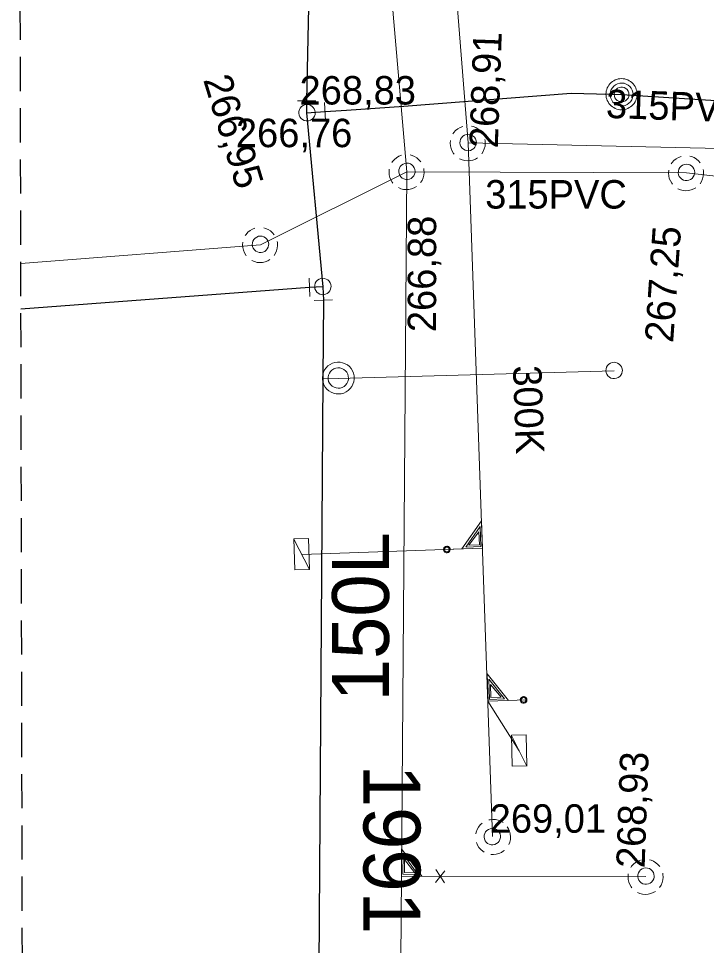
# Model space of a CAD drawing. Extents: x -732074 to -731966, y -1048695 to -1047982.
# Drawn here: x -731995.54 to -731976.2, y -1048660.19 to -1048634.13 of the extents above; entities that cross this region are included whole.
import ezdxf

# ---------------------------------------------------------------- set-up
doc = ezdxf.new("R2010")
doc.units = 0
doc.header["$LTSCALE"] = 0.32
doc.linetypes.add('MEDIUM_DASHED', pattern=[4.5, 3, -1.5])
doc.layers.add('1', color=7, linetype='Continuous')
for name, color, linetype, lineweight in [('18', 7, 'Continuous', 13), ('20', 7, 'Continuous', 13), ('49', 7, 'Continuous', 13), ('63', 7, 'MEDIUM_DASHED', 25), ('8', 7, 'Continuous', 13)]:
    doc.layers.add(name, color=color, linetype=linetype, lineweight=lineweight)

msp = doc.modelspace()

# ---------------------------------------------------------------- linework, layer by layer
at = {"layer": '18'}
for p, q in [((-731987.804, -1048648.765), (-731987.362, -1048649.624)), ((-731981.679, -1048654.282), (-731981.249, -1048655.147)), ((-731983.55, -1048658.088), (-731983.821, -1048658.421)), ((-731983.564, -1048658.426), (-731983.805, -1048658.053))]:
    msp.add_line(p, q, dxfattribs=at)
for points in [[(-731983.052, -1048637.166), (-731983.123, -1048637.194), (-731983.19, -1048637.233), (-731983.25, -1048637.281), (-731983.301, -1048637.338), (-731983.325, -1048637.372)], [(-731982.511, -1048637.349), (-731982.561, -1048637.291), (-731982.619, -1048637.241), (-731982.684, -1048637.2), (-731982.755, -1048637.171), (-731982.804, -1048637.157)], [(-731983.397, -1048637.558), (-731983.402, -1048637.635), (-731983.397, -1048637.712), (-731983.38, -1048637.787), (-731983.352, -1048637.858), (-731983.311, -1048637.924), (-731983.296, -1048637.946)], [(-731982.516, -1048637.935), (-731982.475, -1048637.87), (-731982.444, -1048637.8), (-731982.424, -1048637.725), (-731982.417, -1048637.649), (-731982.422, -1048637.572), (-731982.428, -1048637.537)], [(-731984.773, -1048637.977), (-731984.844, -1048638.005), (-731984.911, -1048638.044), (-731984.971, -1048638.092), (-731985.022, -1048638.149), (-731985.046, -1048638.183)], [(-731984.232, -1048638.16), (-731984.282, -1048638.102), (-731984.34, -1048638.052), (-731984.405, -1048638.011), (-731984.476, -1048637.982), (-731984.525, -1048637.968)], [(-731976.913, -1048638.007), (-731976.984, -1048638.035), (-731977.051, -1048638.074), (-731977.111, -1048638.122), (-731977.162, -1048638.179), (-731977.186, -1048638.213)], [(-731976.372, -1048638.19), (-731976.422, -1048638.132), (-731976.48, -1048638.082), (-731976.545, -1048638.041), (-731976.616, -1048638.012), (-731976.665, -1048637.998)], [(-731983.139, -1048638.075), (-731983.069, -1048638.106), (-731982.994, -1048638.125), (-731982.918, -1048638.132), (-731982.841, -1048638.127), (-731982.766, -1048638.11), (-731982.694, -1048638.082), (-731982.634, -1048638.047)], [(-731985.118, -1048638.369), (-731985.124, -1048638.446), (-731985.119, -1048638.523), (-731985.102, -1048638.598), (-731985.073, -1048638.669), (-731985.032, -1048638.735), (-731985.017, -1048638.757)], [(-731984.237, -1048638.746), (-731984.196, -1048638.681), (-731984.165, -1048638.611), (-731984.146, -1048638.536), (-731984.138, -1048638.46), (-731984.143, -1048638.383), (-731984.149, -1048638.348)], [(-731977.258, -1048638.399), (-731977.264, -1048638.476), (-731977.259, -1048638.553), (-731977.242, -1048638.628), (-731977.213, -1048638.699), (-731977.173, -1048638.765), (-731977.157, -1048638.787)], [(-731976.377, -1048638.776), (-731976.336, -1048638.711), (-731976.305, -1048638.641), (-731976.286, -1048638.566), (-731976.278, -1048638.49), (-731976.283, -1048638.413), (-731976.289, -1048638.378)], [(-731984.86, -1048638.886), (-731984.79, -1048638.917), (-731984.715, -1048638.936), (-731984.639, -1048638.943), (-731984.562, -1048638.938), (-731984.487, -1048638.921), (-731984.415, -1048638.893), (-731984.355, -1048638.858)], [(-731977, -1048638.916), (-731976.93, -1048638.947), (-731976.855, -1048638.966), (-731976.779, -1048638.973), (-731976.702, -1048638.968), (-731976.627, -1048638.951), (-731976.555, -1048638.923), (-731976.495, -1048638.888)], [(-731988.892, -1048640.027), (-731988.963, -1048640.055), (-731989.029, -1048640.094), (-731989.09, -1048640.142), (-731989.141, -1048640.199), (-731989.164, -1048640.233)], [(-731988.35, -1048640.21), (-731988.401, -1048640.152), (-731988.458, -1048640.102), (-731988.524, -1048640.061), (-731988.595, -1048640.032), (-731988.644, -1048640.018)], [(-731989.237, -1048640.419), (-731989.242, -1048640.496), (-731989.237, -1048640.573), (-731989.22, -1048640.648), (-731989.191, -1048640.719), (-731989.151, -1048640.785), (-731989.136, -1048640.807)], [(-731988.355, -1048640.796), (-731988.315, -1048640.731), (-731988.284, -1048640.661), (-731988.264, -1048640.586), (-731988.257, -1048640.51), (-731988.262, -1048640.433), (-731988.267, -1048640.398)], [(-731988.978, -1048640.936), (-731988.909, -1048640.967), (-731988.833, -1048640.986), (-731988.757, -1048640.993), (-731988.681, -1048640.988), (-731988.605, -1048640.971), (-731988.534, -1048640.943), (-731988.473, -1048640.908)], [(-731983.591, -1048649.061), (-731982.497, -1048649.023), (-731982.524, -1048648.252), (-731983.075, -1048649.043)], [(-731982.958, -1048648.988), (-731982.542, -1048648.973), (-731982.562, -1048648.407), (-731982.96, -1048648.988)], [(-731982.876, -1048648.938), (-731982.584, -1048648.928), (-731982.598, -1048648.557), (-731982.876, -1048648.939)], [(-731981.245, -1048653.283), (-731982.339, -1048653.321), (-731982.366, -1048652.552), (-731981.761, -1048653.301)], [(-731981.881, -1048653.255), (-731982.297, -1048653.27), (-731982.317, -1048652.704), (-731981.88, -1048653.255)], [(-731981.967, -1048653.211), (-731982.258, -1048653.221), (-731982.272, -1048652.85), (-731981.967, -1048653.212)], [(-731982.502, -1048656.75), (-731982.558, -1048656.802), (-731982.606, -1048656.861), (-731982.645, -1048656.928), (-731982.672, -1048657), (-731982.684, -1048657.049)], [(-731981.916, -1048656.736), (-731981.982, -1048656.697), (-731982.053, -1048656.668), (-731982.129, -1048656.652), (-731982.205, -1048656.646), (-731982.282, -1048656.654), (-731982.317, -1048656.661)], [(-731981.755, -1048657.354), (-731981.727, -1048657.283), (-731981.71, -1048657.207), (-731981.706, -1048657.131), (-731981.713, -1048657.054), (-731981.733, -1048656.98), (-731981.763, -1048656.909), (-731981.8, -1048656.85)], [(-731982.667, -1048657.297), (-731982.636, -1048657.367), (-731982.595, -1048657.432), (-731982.545, -1048657.491), (-731982.487, -1048657.54), (-731982.452, -1048657.563)], [(-731983.68, -1048658.247), (-731984.775, -1048658.238), (-731984.769, -1048657.469), (-731984.197, -1048658.243)], [(-731982.263, -1048657.629), (-731982.186, -1048657.632), (-731982.11, -1048657.624), (-731982.035, -1048657.605), (-731981.965, -1048657.574), (-731981.9, -1048657.531), (-731981.879, -1048657.515)], [(-731984.316, -1048658.192), (-731984.731, -1048658.189), (-731984.726, -1048657.623), (-731984.314, -1048658.192)], [(-731984.398, -1048658.144), (-731984.69, -1048658.142), (-731984.687, -1048657.77), (-731984.398, -1048658.145)], [(-731978.052, -1048657.787), (-731978.123, -1048657.815), (-731978.19, -1048657.854), (-731978.25, -1048657.902), (-731978.301, -1048657.959), (-731978.325, -1048657.993)], [(-731977.511, -1048657.97), (-731977.561, -1048657.912), (-731977.619, -1048657.862), (-731977.684, -1048657.821), (-731977.755, -1048657.792), (-731977.804, -1048657.778)], [(-731978.397, -1048658.179), (-731978.402, -1048658.256), (-731978.397, -1048658.333), (-731978.38, -1048658.408), (-731978.352, -1048658.479), (-731978.311, -1048658.545), (-731978.296, -1048658.567)], [(-731977.516, -1048658.556), (-731977.475, -1048658.491), (-731977.444, -1048658.421), (-731977.424, -1048658.346), (-731977.417, -1048658.27), (-731977.422, -1048658.193), (-731977.428, -1048658.158)], [(-731978.139, -1048658.696), (-731978.069, -1048658.727), (-731977.994, -1048658.746), (-731977.918, -1048658.753), (-731977.841, -1048658.748), (-731977.766, -1048658.731), (-731977.694, -1048658.703), (-731977.634, -1048658.668)]]:
    msp.add_lwpolyline(points, dxfattribs=at)
for points in [[(-731982.668, -1048637.618), (-731982.674, -1048637.566), (-731982.691, -1048637.516), (-731982.72, -1048637.472), (-731982.758, -1048637.435), (-731982.803, -1048637.408), (-731982.853, -1048637.392), (-731982.905, -1048637.387), (-731982.956, -1048637.394), (-731983.005, -1048637.413), (-731983.049, -1048637.443), (-731983.085, -1048637.482), (-731983.111, -1048637.527), (-731983.125, -1048637.578), (-731983.129, -1048637.63), (-731983.12, -1048637.682), (-731983.1, -1048637.73), (-731983.07, -1048637.773), (-731983.03, -1048637.808), (-731982.983, -1048637.832), (-731982.933, -1048637.846), (-731982.88, -1048637.848), (-731982.829, -1048637.838), (-731982.781, -1048637.816), (-731982.739, -1048637.784), (-731982.706, -1048637.744), (-731982.682, -1048637.697), (-731982.669, -1048637.646)], [(-731984.389, -1048638.429), (-731984.395, -1048638.377), (-731984.413, -1048638.327), (-731984.441, -1048638.283), (-731984.479, -1048638.246), (-731984.524, -1048638.219), (-731984.574, -1048638.203), (-731984.626, -1048638.198), (-731984.678, -1048638.205), (-731984.727, -1048638.224), (-731984.771, -1048638.254), (-731984.806, -1048638.293), (-731984.832, -1048638.338), (-731984.847, -1048638.389), (-731984.85, -1048638.441), (-731984.842, -1048638.493), (-731984.821, -1048638.541), (-731984.791, -1048638.584), (-731984.751, -1048638.619), (-731984.705, -1048638.643), (-731984.654, -1048638.657), (-731984.602, -1048638.659), (-731984.55, -1048638.649), (-731984.502, -1048638.627), (-731984.46, -1048638.595), (-731984.427, -1048638.555), (-731984.403, -1048638.508), (-731984.391, -1048638.457)], [(-731976.529, -1048638.459), (-731976.535, -1048638.407), (-731976.553, -1048638.357), (-731976.581, -1048638.313), (-731976.619, -1048638.276), (-731976.664, -1048638.249), (-731976.714, -1048638.233), (-731976.766, -1048638.228), (-731976.818, -1048638.235), (-731976.867, -1048638.254), (-731976.911, -1048638.284), (-731976.946, -1048638.323), (-731976.972, -1048638.368), (-731976.987, -1048638.419), (-731976.99, -1048638.471), (-731976.982, -1048638.523), (-731976.961, -1048638.571), (-731976.931, -1048638.614), (-731976.891, -1048638.649), (-731976.845, -1048638.673), (-731976.794, -1048638.687), (-731976.742, -1048638.689), (-731976.69, -1048638.679), (-731976.642, -1048638.657), (-731976.6, -1048638.625), (-731976.567, -1048638.585), (-731976.543, -1048638.538), (-731976.531, -1048638.487)], [(-731988.507, -1048640.479), (-731988.514, -1048640.427), (-731988.531, -1048640.377), (-731988.559, -1048640.333), (-731988.598, -1048640.296), (-731988.642, -1048640.269), (-731988.693, -1048640.253), (-731988.745, -1048640.248), (-731988.796, -1048640.255), (-731988.845, -1048640.274), (-731988.889, -1048640.304), (-731988.924, -1048640.343), (-731988.951, -1048640.388), (-731988.965, -1048640.439), (-731988.968, -1048640.491), (-731988.96, -1048640.543), (-731988.94, -1048640.591), (-731988.909, -1048640.634), (-731988.87, -1048640.669), (-731988.823, -1048640.693), (-731988.772, -1048640.707), (-731988.72, -1048640.709), (-731988.669, -1048640.699), (-731988.62, -1048640.677), (-731988.578, -1048640.645), (-731988.546, -1048640.605), (-731988.522, -1048640.558), (-731988.509, -1048640.507)], [(-731987.392, -1048648.747), (-731987.363, -1048649.62), (-731987.774, -1048649.634), (-731987.804, -1048648.761)], [(-731983.501, -1048648.963), (-731983.534, -1048648.97), (-731983.562, -1048648.988), (-731983.582, -1048649.015), (-731983.591, -1048649.047), (-731983.589, -1048649.08), (-731983.575, -1048649.111), (-731983.551, -1048649.135), (-731983.52, -1048649.149), (-731983.487, -1048649.152), (-731983.454, -1048649.141), (-731983.428, -1048649.122), (-731983.41, -1048649.094), (-731983.403, -1048649.061), (-731983.407, -1048649.028), (-731983.423, -1048648.998), (-731983.449, -1048648.976), (-731983.481, -1048648.964)], [(-731983.498, -1048648.99), (-731983.526, -1048648.997), (-731983.548, -1048649.015), (-731983.561, -1048649.039), (-731983.562, -1048649.068), (-731983.552, -1048649.094), (-731983.532, -1048649.114), (-731983.506, -1048649.124), (-731983.477, -1048649.122), (-731983.453, -1048649.108), (-731983.435, -1048649.087), (-731983.428, -1048649.059), (-731983.433, -1048649.032), (-731983.45, -1048649.008), (-731983.475, -1048648.993)], [(-731981.342, -1048653.192), (-731981.375, -1048653.199), (-731981.403, -1048653.217), (-731981.423, -1048653.244), (-731981.432, -1048653.276), (-731981.43, -1048653.309), (-731981.416, -1048653.34), (-731981.392, -1048653.364), (-731981.361, -1048653.378), (-731981.328, -1048653.38), (-731981.297, -1048653.371), (-731981.269, -1048653.351), (-731981.251, -1048653.322), (-731981.244, -1048653.29), (-731981.249, -1048653.256), (-731981.265, -1048653.226), (-731981.29, -1048653.205), (-731981.322, -1048653.193)], [(-731981.342, -1048653.219), (-731981.37, -1048653.226), (-731981.392, -1048653.243), (-731981.404, -1048653.268), (-731981.406, -1048653.296), (-731981.396, -1048653.323), (-731981.376, -1048653.342), (-731981.349, -1048653.352), (-731981.321, -1048653.35), (-731981.297, -1048653.337), (-731981.28, -1048653.315), (-731981.272, -1048653.288), (-731981.277, -1048653.26), (-731981.294, -1048653.236), (-731981.318, -1048653.222)], [(-731981.267, -1048654.269), (-731981.249, -1048655.143), (-731981.661, -1048655.152), (-731981.679, -1048654.278)], [(-731982.228, -1048656.898), (-731982.279, -1048656.906), (-731982.329, -1048656.925), (-731982.372, -1048656.955), (-731982.408, -1048656.994), (-731982.433, -1048657.04), (-731982.447, -1048657.09), (-731982.451, -1048657.142), (-731982.442, -1048657.194), (-731982.421, -1048657.243), (-731982.39, -1048657.286), (-731982.35, -1048657.319), (-731982.304, -1048657.344), (-731982.252, -1048657.357), (-731982.2, -1048657.358), (-731982.149, -1048657.349), (-731982.101, -1048657.326), (-731982.059, -1048657.295), (-731982.026, -1048657.253), (-731982.003, -1048657.207), (-731981.991, -1048657.155), (-731981.991, -1048657.103), (-731982.002, -1048657.052), (-731982.026, -1048657.004), (-731982.059, -1048656.963), (-731982.1, -1048656.932), (-731982.148, -1048656.909), (-731982.2, -1048656.899)], [(-731977.668, -1048658.239), (-731977.674, -1048658.187), (-731977.691, -1048658.137), (-731977.72, -1048658.093), (-731977.758, -1048658.056), (-731977.803, -1048658.029), (-731977.853, -1048658.013), (-731977.905, -1048658.008), (-731977.956, -1048658.015), (-731978.005, -1048658.034), (-731978.049, -1048658.064), (-731978.085, -1048658.103), (-731978.111, -1048658.148), (-731978.125, -1048658.199), (-731978.129, -1048658.251), (-731978.12, -1048658.303), (-731978.1, -1048658.351), (-731978.07, -1048658.394), (-731978.03, -1048658.429), (-731977.983, -1048658.453), (-731977.933, -1048658.467), (-731977.88, -1048658.469), (-731977.829, -1048658.459), (-731977.781, -1048658.437), (-731977.739, -1048658.405), (-731977.706, -1048658.365), (-731977.682, -1048658.318), (-731977.669, -1048658.267)]]:
    msp.add_lwpolyline(points, close=True, dxfattribs=at)
at = {"layer": '20'}
msp.add_line((-731982.21, -1048657.129), (-731982.899, -1048637.629), dxfattribs=at)
msp.add_line((-731982.21, -1048657.129), (-731982.899, -1048637.629), dxfattribs=at)
for points in [[(-731984.62, -1048638.44), (-731986.574, -1048615.933), (-731987.18, -1048608.96)], [(-731984.62, -1048638.44), (-731986.574, -1048615.933), (-731987.18, -1048608.96)], [(-731969.16, -1048637.94), (-731982.899, -1048637.629), (-731984.98, -1048611.47)], [(-731969.16, -1048637.94), (-731982.899, -1048637.629), (-731984.98, -1048611.47)], [(-731995.477, -1048641.021), (-731988.739, -1048640.49), (-731984.62, -1048638.44)], [(-731995.477, -1048641.021), (-731988.739, -1048640.49), (-731984.62, -1048638.44)], [(-731985, -1048686.94), (-731984.895, -1048673.539), (-731984.774, -1048658.239), (-731984.62, -1048638.44)], [(-731985, -1048686.94), (-731984.895, -1048673.539), (-731984.774, -1048658.239), (-731984.62, -1048638.44)], [(-731966.829, -1048639.601), (-731976.76, -1048638.47), (-731984.62, -1048638.44)], [(-731966.829, -1048639.601), (-731976.76, -1048638.47), (-731984.62, -1048638.44)]]:
    msp.add_lwpolyline(points, dxfattribs=at)
at = {"layer": '49'}
for p, q in [((-731987.579, -1048649.2), (-731982.496, -1048649.024)), ((-731987.579, -1048649.2), (-731982.496, -1048649.024)), ((-731981.46, -1048654.72), (-731982.344, -1048653.321)), ((-731981.46, -1048654.72), (-731982.344, -1048653.321)), ((-731977.899, -1048658.25), (-731984.774, -1048658.239)), ((-731977.899, -1048658.25), (-731984.774, -1048658.239))]:
    msp.add_line(p, q, dxfattribs=at)
at = {"layer": '63'}
msp.add_lwpolyline([(-731967.071, -1048608.115), (-731966.405, -1048694.807), (-731966.405, -1048694.809), (-731966.406, -1048694.811), (-731966.407, -1048694.813), (-731966.408, -1048694.814), (-731966.409, -1048694.816), (-731966.411, -1048694.817), (-731966.413, -1048694.817), (-731966.415, -1048694.818), (-731966.417, -1048694.817), (-731995.356, -1048690.903), (-731995.358, -1048690.903), (-731995.36, -1048690.902), (-731995.362, -1048690.901), (-731995.363, -1048690.899), (-731995.364, -1048690.897), (-731995.365, -1048690.895), (-731995.365, -1048690.893), (-731995.541, -1048612.001)], dxfattribs=at)
at = {"layer": '8'}
for p, q in [((-731987.18, -1048636.45), (-731987.697, -1048636.449)), ((-731986.934, -1048636.49), (-731986.905, -1048637.007)), ((-731987.348, -1048641.949), (-731987.369, -1048641.432)), ((-731986.709, -1048642.039), (-731987.226, -1048642.058)), ((-731986.55, -1048644.25), (-731978.795, -1048644.036)), ((-731986.984, -1048644.243), (-731986.55, -1048644.25))]:
    msp.add_line(p, q, dxfattribs=at)
at = {"layer": '8', "lineweight": 25}
for p, q in [((-731987.44, -1048636.78), (-731986.92, -1048636.75)), ((-731987.359, -1048641.69), (-731995.474, -1048642.298)), ((-731986.984, -1048641.676), (-731986.969, -1048642.05))]:
    msp.add_line(p, q, dxfattribs=at)
for points in [[(-731990.289, -1048609.03), (-731989.399, -1048614.955), (-731989.079, -1048616.929), (-731987.35, -1048632.04), (-731987.44, -1048636.45)], [(-731987.44, -1048636.45), (-731987.44, -1048636.78), (-731986.984, -1048641.676), (-731987.359, -1048641.69)], [(-731986.92, -1048636.75), (-731986.62, -1048636.73), (-731986.32, -1048636.71), (-731984.71, -1048636.6), (-731980, -1048636.23), (-731978.579, -1048636.27)], [(-731978.579, -1048636.27), (-731974.02, -1048636.56), (-731968.19, -1048637.159), (-731966.847, -1048637.321)], [(-731986.969, -1048642.05), (-731986.984, -1048644.243), (-731987.12, -1048663.55), (-731987.35, -1048670.27), (-731987.388, -1048681.801), (-731987.43, -1048684.57)]]:
    msp.add_lwpolyline(points, dxfattribs=at)
at = {"layer": '8'}
msp.add_lwpolyline([(-731978.149, -1048636.259), (-731978.151, -1048636.214), (-731978.158, -1048636.169), (-731978.17, -1048636.124), (-731978.186, -1048636.082), (-731978.207, -1048636.041), (-731978.232, -1048636.002), (-731978.261, -1048635.967), (-731978.293, -1048635.934), (-731978.329, -1048635.906), (-731978.367, -1048635.881), (-731978.408, -1048635.86), (-731978.451, -1048635.843), (-731978.495, -1048635.831), (-731978.54, -1048635.824), (-731978.586, -1048635.822), (-731978.632, -1048635.824), (-731978.677, -1048635.831), (-731978.721, -1048635.843), (-731978.764, -1048635.86), (-731978.805, -1048635.881), (-731978.843, -1048635.906), (-731978.879, -1048635.934), (-731978.911, -1048635.967), (-731978.94, -1048636.002), (-731978.965, -1048636.041), (-731978.986, -1048636.082), (-731979.002, -1048636.124), (-731979.014, -1048636.169), (-731979.021, -1048636.214), (-731979.024, -1048636.26), (-731979.021, -1048636.305), (-731979.014, -1048636.35), (-731979.002, -1048636.395), (-731978.986, -1048636.437), (-731978.965, -1048636.478), (-731978.94, -1048636.517), (-731978.911, -1048636.552), (-731978.879, -1048636.585), (-731978.843, -1048636.613), (-731978.805, -1048636.638), (-731978.764, -1048636.659), (-731978.721, -1048636.676), (-731978.677, -1048636.687), (-731978.632, -1048636.695), (-731978.586, -1048636.697), (-731978.54, -1048636.695), (-731978.495, -1048636.687), (-731978.451, -1048636.676), (-731978.408, -1048636.659), (-731978.367, -1048636.638), (-731978.329, -1048636.613), (-731978.293, -1048636.585), (-731978.261, -1048636.552), (-731978.232, -1048636.517), (-731978.207, -1048636.478), (-731978.186, -1048636.437), (-731978.17, -1048636.395), (-731978.158, -1048636.35), (-731978.151, -1048636.305), (-731978.149, -1048636.26)], dxfattribs=at)
for points in [[(-731978.262, -1048636.267), (-731978.268, -1048636.206), (-731978.286, -1048636.146), (-731978.315, -1048636.091), (-731978.354, -1048636.043), (-731978.401, -1048636.003), (-731978.455, -1048635.973), (-731978.514, -1048635.953), (-731978.576, -1048635.946), (-731978.638, -1048635.95), (-731978.698, -1048635.966), (-731978.753, -1048635.994), (-731978.803, -1048636.031), (-731978.844, -1048636.078), (-731978.876, -1048636.131), (-731978.896, -1048636.19), (-731978.906, -1048636.251), (-731978.903, -1048636.313), (-731978.888, -1048636.373), (-731978.862, -1048636.43), (-731978.826, -1048636.48), (-731978.78, -1048636.523), (-731978.728, -1048636.555), (-731978.67, -1048636.578), (-731978.609, -1048636.588), (-731978.547, -1048636.587), (-731978.486, -1048636.574), (-731978.429, -1048636.549), (-731978.378, -1048636.514), (-731978.334, -1048636.47), (-731978.3, -1048636.418), (-731978.276, -1048636.361), (-731978.264, -1048636.3)], [(-731978.376, -1048636.267), (-731978.382, -1048636.218), (-731978.399, -1048636.171), (-731978.427, -1048636.13), (-731978.465, -1048636.097), (-731978.509, -1048636.073), (-731978.557, -1048636.061), (-731978.607, -1048636.06), (-731978.655, -1048636.072), (-731978.7, -1048636.094), (-731978.738, -1048636.127), (-731978.767, -1048636.167), (-731978.786, -1048636.214), (-731978.793, -1048636.263), (-731978.788, -1048636.313), (-731978.771, -1048636.36), (-731978.744, -1048636.402), (-731978.707, -1048636.436), (-731978.664, -1048636.46), (-731978.616, -1048636.474), (-731978.566, -1048636.475), (-731978.517, -1048636.465), (-731978.472, -1048636.443), (-731978.433, -1048636.411), (-731978.403, -1048636.372), (-731978.384, -1048636.326), (-731978.376, -1048636.276)], [(-731987.429, -1048637.011), (-731987.377, -1048637.005), (-731987.327, -1048636.987), (-731987.283, -1048636.959), (-731987.246, -1048636.921), (-731987.219, -1048636.876), (-731987.203, -1048636.826), (-731987.198, -1048636.774), (-731987.205, -1048636.722), (-731987.224, -1048636.673), (-731987.254, -1048636.629), (-731987.293, -1048636.594), (-731987.338, -1048636.568), (-731987.389, -1048636.553), (-731987.441, -1048636.55), (-731987.493, -1048636.557), (-731987.541, -1048636.578), (-731987.584, -1048636.608), (-731987.619, -1048636.648), (-731987.643, -1048636.694), (-731987.657, -1048636.745), (-731987.659, -1048636.797), (-731987.649, -1048636.849), (-731987.627, -1048636.897), (-731987.595, -1048636.939), (-731987.555, -1048636.972), (-731987.508, -1048636.996), (-731987.457, -1048637.008)], [(-731986.753, -1048641.665), (-731986.759, -1048641.613), (-731986.777, -1048641.563), (-731986.805, -1048641.519), (-731986.843, -1048641.482), (-731986.888, -1048641.455), (-731986.938, -1048641.439), (-731986.99, -1048641.434), (-731987.042, -1048641.441), (-731987.091, -1048641.46), (-731987.135, -1048641.49), (-731987.17, -1048641.529), (-731987.196, -1048641.574), (-731987.211, -1048641.625), (-731987.214, -1048641.677), (-731987.206, -1048641.729), (-731987.185, -1048641.777), (-731987.155, -1048641.82), (-731987.115, -1048641.855), (-731987.069, -1048641.879), (-731987.018, -1048641.893), (-731986.966, -1048641.895), (-731986.914, -1048641.885), (-731986.866, -1048641.863), (-731986.824, -1048641.831), (-731986.791, -1048641.791), (-731986.767, -1048641.744), (-731986.755, -1048641.693)], [(-731986.102, -1048644.246), (-731986.107, -1048644.173), (-731986.124, -1048644.102), (-731986.152, -1048644.034), (-731986.191, -1048643.973), (-731986.239, -1048643.917), (-731986.295, -1048643.871), (-731986.359, -1048643.835), (-731986.427, -1048643.809), (-731986.499, -1048643.795), (-731986.573, -1048643.793), (-731986.645, -1048643.802), (-731986.716, -1048643.824), (-731986.78, -1048643.856), (-731986.84, -1048643.899), (-731986.892, -1048643.951), (-731986.934, -1048644.011), (-731986.966, -1048644.077), (-731986.987, -1048644.147), (-731986.996, -1048644.22), (-731986.993, -1048644.293), (-731986.978, -1048644.364), (-731986.953, -1048644.433), (-731986.916, -1048644.496), (-731986.868, -1048644.552), (-731986.813, -1048644.6), (-731986.751, -1048644.638), (-731986.683, -1048644.666), (-731986.611, -1048644.682), (-731986.539, -1048644.686), (-731986.465, -1048644.678), (-731986.395, -1048644.659), (-731986.329, -1048644.628), (-731986.268, -1048644.587), (-731986.215, -1048644.536), (-731986.171, -1048644.477), (-731986.137, -1048644.413), (-731986.115, -1048644.343), (-731986.104, -1048644.271)], [(-731986.263, -1048644.244), (-731986.268, -1048644.186), (-731986.286, -1048644.129), (-731986.313, -1048644.078), (-731986.351, -1048644.033), (-731986.396, -1048643.996), (-731986.449, -1048643.971), (-731986.506, -1048643.956), (-731986.565, -1048643.953), (-731986.622, -1048643.962), (-731986.677, -1048643.983), (-731986.727, -1048644.014), (-731986.768, -1048644.054), (-731986.801, -1048644.103), (-731986.824, -1048644.158), (-731986.835, -1048644.214), (-731986.834, -1048644.273), (-731986.821, -1048644.331), (-731986.797, -1048644.384), (-731986.761, -1048644.431), (-731986.718, -1048644.47), (-731986.668, -1048644.499), (-731986.612, -1048644.518), (-731986.554, -1048644.525), (-731986.496, -1048644.52), (-731986.44, -1048644.504), (-731986.388, -1048644.476), (-731986.344, -1048644.437), (-731986.308, -1048644.392), (-731986.282, -1048644.339), (-731986.267, -1048644.283)], [(-731978.563, -1048644.029), (-731978.569, -1048643.977), (-731978.586, -1048643.926), (-731978.613, -1048643.882), (-731978.65, -1048643.844), (-731978.695, -1048643.817), (-731978.745, -1048643.8), (-731978.797, -1048643.794), (-731978.849, -1048643.8), (-731978.898, -1048643.818), (-731978.942, -1048643.848), (-731978.978, -1048643.886), (-731979.005, -1048643.931), (-731979.021, -1048643.981), (-731979.024, -1048644.033), (-731979.017, -1048644.085), (-731978.997, -1048644.134), (-731978.968, -1048644.177), (-731978.928, -1048644.213), (-731978.883, -1048644.238), (-731978.832, -1048644.252), (-731978.78, -1048644.255), (-731978.728, -1048644.246), (-731978.68, -1048644.225), (-731978.637, -1048644.194), (-731978.603, -1048644.154), (-731978.579, -1048644.108), (-731978.566, -1048644.057)]]:
    msp.add_lwpolyline(points, close=True, dxfattribs=at)

# ---------------------------------------------------------------- texts
at = {"layer": '1'}
for s, height, rotation, p in [('268,91', 0.8, 88, (-731982.066, -1048637.786)), ('266,95', 0.8, 287, (-731990.354, -1048635.85)), ('315PVC', 0.8, 358, (-731979.032, -1048636.925)), ('266,88', 0.8, 90, (-731983.798, -1048642.948)), ('267,25', 0.8, 86, (-731977.136, -1048643.26)), ('300K', 0.8, 272, (-731981.64, -1048643.893)), ('150L', 1.6, 90, (-731985.125, -1048653.326)), ('268,93', 0.8, 88, (-731977.937, -1048658.024)), ('1991', 1.6, 270, (-731985.842, -1048655.106))]:
    msp.add_text(s, height=height, rotation=rotation, dxfattribs=at).set_placement(p)
for s, p in [('268,83', (-731987.639, -1048636.55)), ('266,76', (-731989.429, -1048637.749)), ('315PVC', (-731982.42, -1048639.474)), ('269,01', (-731982.292, -1048657.02))]:
    msp.add_text(s, height=0.8, dxfattribs=at).set_placement(p)

doc.saveas('drawing.dxf')
